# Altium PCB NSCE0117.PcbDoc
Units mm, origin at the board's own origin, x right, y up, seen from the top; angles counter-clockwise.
Board outline 36.5 x 20.1 mm, 2 copper layers (Top Layer, Bottom Layer); 46 components, 30 nets, 110 pads, 14 vias.
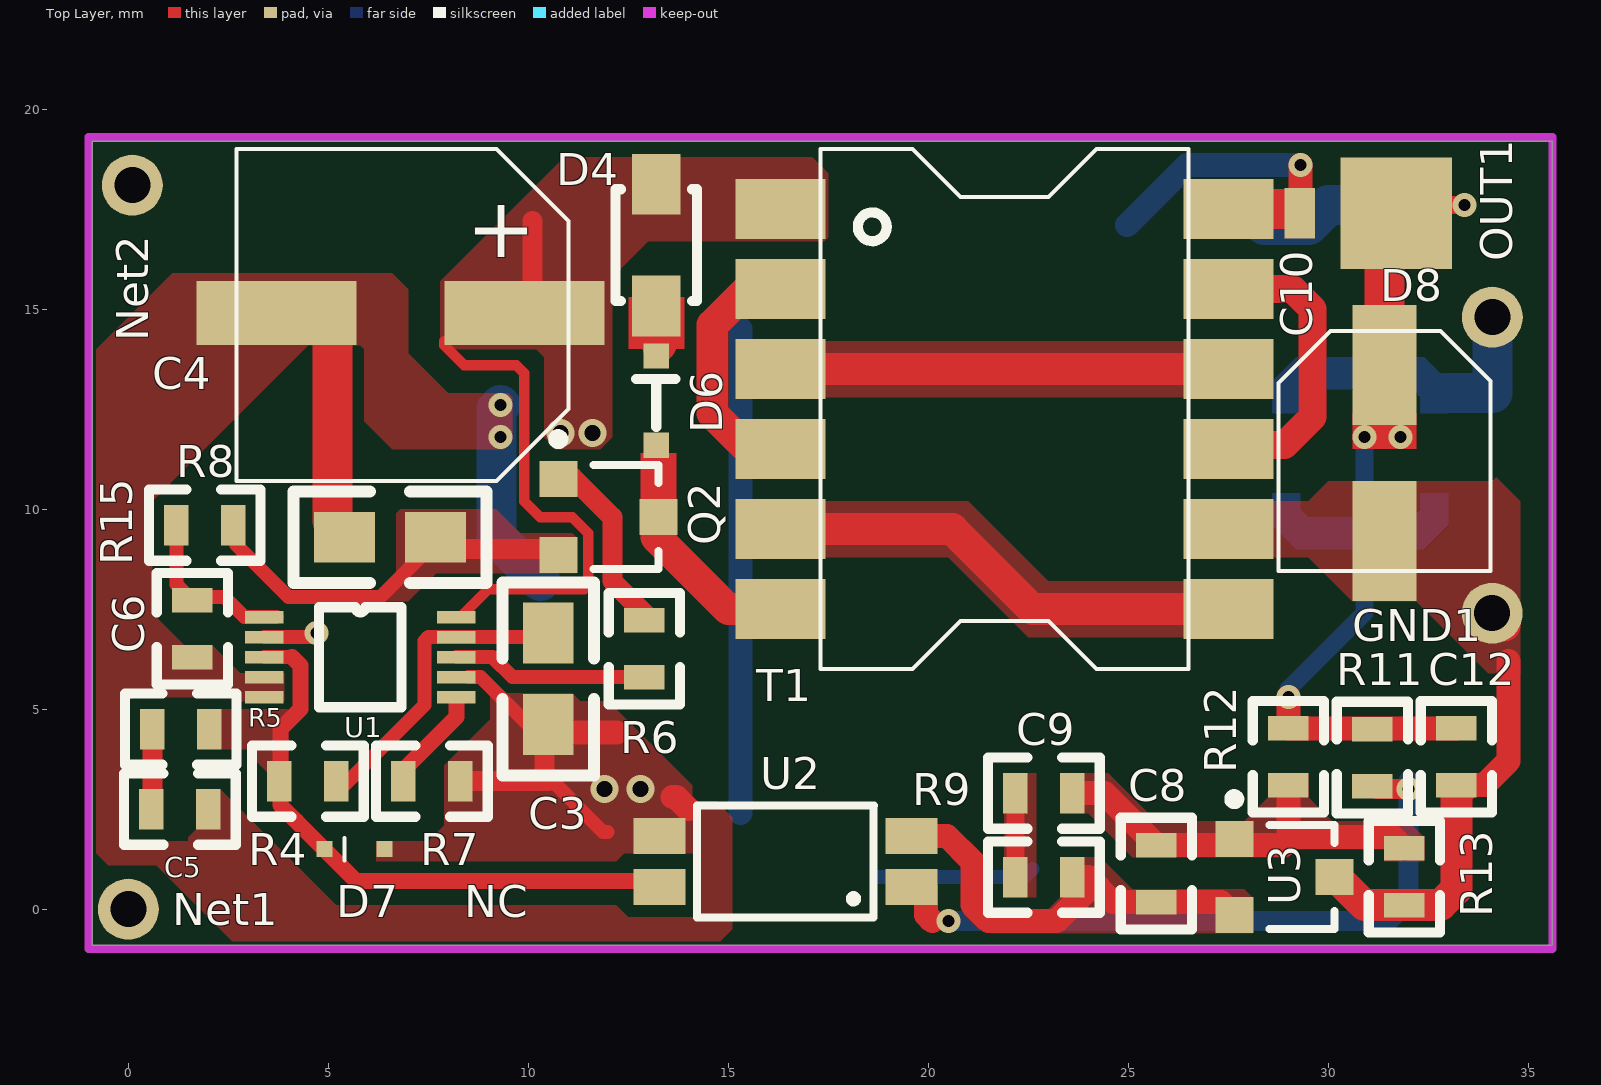
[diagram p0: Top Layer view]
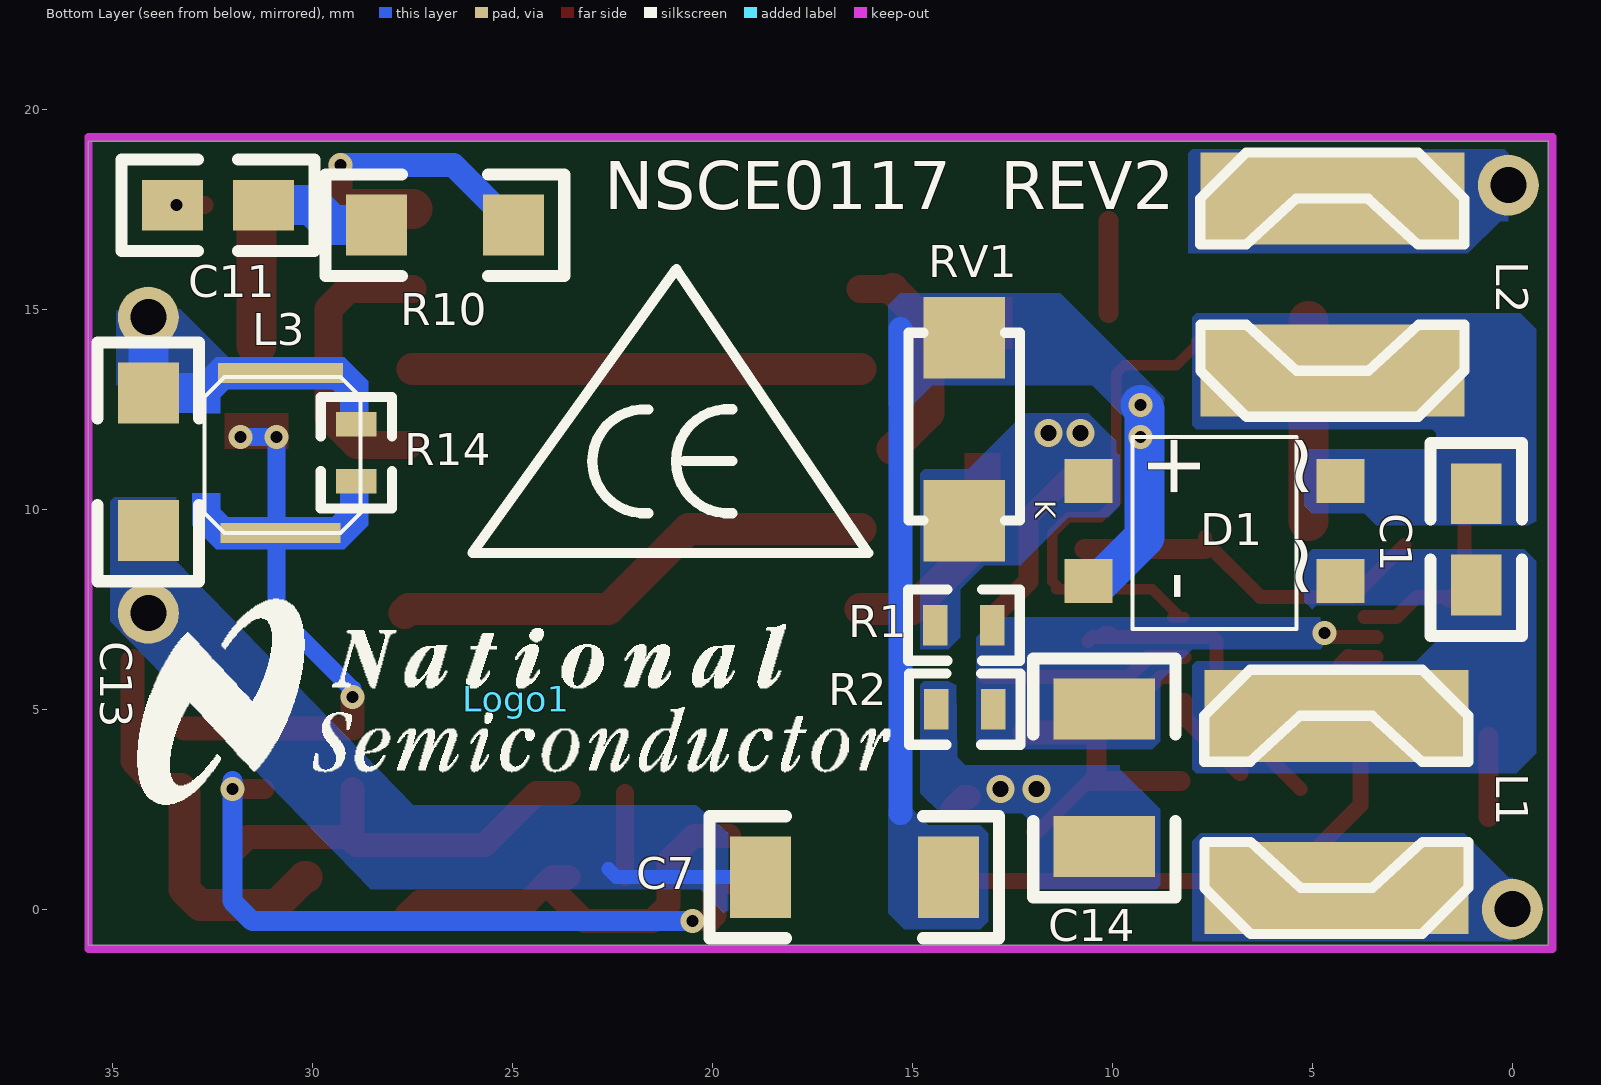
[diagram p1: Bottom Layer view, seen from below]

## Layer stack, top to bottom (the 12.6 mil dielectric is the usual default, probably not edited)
Top Layer: signal copper 0.0356
Dielectric: core 0.32, FR-4, Dk 4.8
Bottom Layer: signal copper 0.0356

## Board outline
-0.9,-0.9 35.6,-0.9 35.6,19.2 -0.9,19.2 -0.9,-0.9

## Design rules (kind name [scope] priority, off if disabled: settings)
AssemblyTestPointUsage [All] p1: valid=2
Clearance [All] p1: gap=0.1
ComponentClearance [All] p1: gap=0.1 collisioncheckmode=3 verticalgap=0.254 showdistances=FALSE
FabricationTestPointUsage TestPointUsage [All] p1: valid=2 allowmultiple=FALSE
FabricationTestpoint Testpoint [All] p1: side=3 testpointundercomponent=TRUE minsize=1.016 maxsize=2.54 preferedsize=1.524 minholesize=0 maxholesize=1.016 preferedholesize=0.813 testpointgrid=0.025 allowsidetop=TRUE allowsidebottom=TRUE usegrid=TRUE gridtolerance=0
MinimumSolderMaskSliver [All] p1: minsoldermaskwidth=0.102
PlaneClearance [All] p1: clearance=0.2
PolygonConnect [All] p1: connectstyle=Direct reliefconductorwidth=0.254 reliefentries=4 polygonreliefangle="90 Angle"
RoutingVias [All] p1: holewidth=0.711 width=1.27 viastyle="Through Hole" minholewidth=0.711 minwidth=1.27 maxholewidth=0.711 maxwidth=1.27
SilkToSilkClearance [All] p1: silktosilkclearance=0.127
SilkscreenOverComponentPads [All] p1: minsilkscreentomaskgap=0.127
SolderMaskExpansion [All] p1: expansion=0.102
Width [All] p1: maxlimit=1.5 minlimit=0.1 preferedwidth=0.254
20 further rules are at their usual default settings.

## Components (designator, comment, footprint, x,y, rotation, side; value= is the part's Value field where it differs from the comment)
C1 "C0805C104K5RACTU" 0805 0.9,8.1 r90 bottom
C3 "C0805C224K3RACTU" 0805 10.5,6.9 r270 top
C4 "EEEFK1H470P" "Panasonic E-Series AluCap" 9.9,14.9 r180 top
C5 "C0603C103K5RACTU" 0603 2,2.5 r180 top
C6 "Not specified" 0603 1.6,6.3 r90 top
C7 "C1808C821KHRAC" 1808 14.1,0.8 r0 bottom
C8 "C0603C101J5GAC" 0603 25.7,1.6 r270 top
C9 "C0603C103K5RACTU" 0603 23.6,2.9 r180 top
C10 "4SVPC150MY" "OS-CON CaseB6 Sanyo" 31.4,13.6 r270 top
C11 "C0805C221J1GAC" 0805 33.5,17.6 r180 bottom
C12 "C0805C104K5RAC" 0603 33.2,3.1 r90 top
C13 "C1206C104K5RAC" 1206 34.1,12.9 r270 bottom
C14 "C1210C226K4PAC" 1210 10.2,5 r270 bottom
D1 "CBRHD-02 LEAD FREE" "Optocoupler CBRHD-xx Central" 4.3,8.2 r90 bottom
D4 "CMHZ4709 LEAD FREE" SOD-123 13.2,16.6 r270 top
D6 "CMDD4448 LEAD FREE" sod-323 13.2,11.6 r90 top (schematic designator D3)
D7 "CMOZ4L7 LEAD FREE" SOD-523 4.9,1.5 r270 top
D8 "SS1P4-M3/84A" DO-220AA 31.7,17.4 r180 top (schematic designator D5)
GND1 "" PCBPin_GoldenNeedle 34.099,7.399 r90 top
L1 "LPS6235-225MLB" Ind_LPS6235 4.4,0.4 r90 bottom
L2 "LPS6235-225MLB" Ind_LPS6235 4.5,17.9 r270 bottom
L3 "LPS4018-xxxMLB" "LPS4018 Coilcraft" 30.8,11.4 r90 bottom
Logo1 "" Logo_Overlay_Medium 24.9,5.25 r180 bottom
Net1 "" PCBPin_GoldenNeedle 0,0 r90 top
Net2 "" PCBPin_GoldenNeedle 0.1,18.1 r90 top
OUT1 "" PCBPin_GoldenNeedle 34.1,14.8 r90 top
Q2 "CPH3427-TL-E" SOT-23 12,9.8 r270 top
R1 "" 0603 13,7.1 r0 bottom
R2 "" 0603 14.4,5 r180 bottom
R4 "" 0603 5.2,3.2 r180 top
R5 "" 0603 0.6,4.5 r0 top
R6 "" 0603 12.9,5.8 r90 top
R7 "" 0603 8.3,3.2 r180 top
R8 "" 0805 5.4,9.3 r0 top
R9 "" 0603 23.6,0.8 r180 top
R10 "" 1206 28.4,17.1 r180 bottom
R11 "" 0603 31.1,4.5 r270 top
R12 "" 0603 29,3.1 r90 top
R13 "" 0603 31.9,0.1 r90 top
R14 "" 0603 28.9,10.7 r90 bottom
R15 "" 0603 1.2,9.6 r0 top
RV1 "SMAJ40CA-E3/61" SMA 13.7,12 r270 bottom
T1 "PCA11/5ER-U07S002" "XFMR-ER11/5 Series Wuerth" 16.3,17.5 r270 top (schematic designator T?)
U1 "LM3481MM/NOPB" MSOP-10 3.4,7.3 r0 top
U2 "TCMT1103" SOP-8 14.5,3.1 r180 top
U3 "LMV431AIMF/NOPB" SOT-23 28.9,0.8 r270 top

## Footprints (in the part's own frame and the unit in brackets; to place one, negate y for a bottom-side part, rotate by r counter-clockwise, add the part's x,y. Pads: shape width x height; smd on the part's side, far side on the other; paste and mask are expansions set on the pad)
0603 [mil]
  rect 24x40 smd: 1(0,0) 2(56,0)
  silkscreen extent -27,-35 83,35
0805 [mil]
  rect 60x50 smd: 1(0,0) 2(90,0)
  silkscreen extent -50,-45 140,45
1206 [mil]
  rect 60x60 smd: 1(0,0) 2(135,0)
  silkscreen extent -50,-50 185,50
1210 [mil]
  rect 60x100 smd: 1(0,0) 2(135,0)
  silkscreen extent -50,-70 185,70
1808 [mil]
  rect 60x80 smd: 1(0,0) 2(185,0)
  silkscreen extent -50,-60 235,60
DO-220AA [mil]
  rect 30x50 smd: 1(95,0)
  rect 110x110 smd: 2(0,0)
Ind_LPS6235 [mm] "Coilcraft LPS6235"
  rect 2.3x6.6 smd: 1(0.127,0) 2(4.427,0)
  silkscreen extent -1.02,-3.3 5.59,3.3
Logo_Overlay_Medium [mm]
  silkscreen extent -9.47,-2.64 9.35,2.51
"LPS4018 Coilcraft" [mm] "LPS4018 Coilcraft"
  rect 0.5x3 smd: 1(-2,0)
  rect 0.5x3.124 smd: 2(2,0)
  Top Layer region: -2.4,1.6 -1.8,2.2 -1,2.2 -1,1.5 -1.4,1.5 -1.6,1.3 -1.6,-1.3 -1.4,-1.5 -1,-1.5 -1,-2.2 -1.8,-2.2 -2.4,-1.6
  Top Layer region: 2.4,-1.6 1.8,-2.2 1,-2.2 1,-1.5 1.4,-1.5 1.6,-1.3 1.6,1.3 1.4,1.5 1,1.5 1,2.2 1.8,2.2 2.4,1.6
  silkscreen extent -2,-2 1.9,1.9
MSOP-10 [mil]
  rect 38x12 smd: 1(0,0) 2(0,-19.7) 3(0,-39.4) 4(0,-59.1) 5(0,-78.8) 6(189,-78.8) 7(189,-59.1) 8(189,-39.4) 9(189,-19.7) 10(189,0)
  silkscreen extent 54,-89 135,10
"Optocoupler CBRHD-xx Central" [mm] "Optocoupler CBRHD-xx Central"
  rect 1.1x1.2 smd: 1(0,0) 2(2.5,0) 3(2.5,6.3) 4(0,6.3)
  silkscreen extent -1.2,1.1 3.6,5.2
"OS-CON CaseB6 Sanyo" [mm] "OS-CON CaseB6 Sanyo"
  rect 3x1.6 smd: 1(0,0) 2(4.4,0)
  silkscreen extent -0.85,-2.65 5.15,2.65
"Panasonic E-Series AluCap" [mm] "Panasonic E-Series AluCap"
  rect 4x1.6 smd: 1(0,0) 2(6.2,0)
  silkscreen extent -1.1,-4.1 7.2,4.2
PCBPin_GoldenNeedle [mil] "PCBPin_GoldenNeedle"
  round 60 hole 35.43: 1(0,0)
SMA [mil]
  rect 80x80 smd: 1(-90,0) 2(90,0)
  silkscreen extent -95,-55 90,55
SOD-123 [mil]
  rect 60x48 smd: 1(-60,0) 2(60,0)
  silkscreen extent -55,-40 55,40
sod-323 [mm]
  rect 0.63x0.63 smd: 1(0,0) 2(2.23,0)
  silkscreen extent 0.46,-0.48 1.65,0.51
SOD-523 [mm]
  rect 0.4x0.4 smd: 1(0,1.5) 2(0,0)
  silkscreen extent -0.28,0.51 0.28,0.51
SOP-8 [mm] "SOP-8 (TCMT1100 Optocoupler)"
  rect 1.3x0.9 smd: 1(-5.08,2.54) 2(-5.08,1.27) 3(1.22,1.27) 4(1.22,2.54)
  silkscreen extent -4.14,0.51 0.28,3.31
SOT-23 [mm] "SOT-23; 3 Leads; Body 3.0 x 2.6 mm, inc. leads (LxW max)"
  rect 0.9x0.95 smd: 1(-0.95,-1.25) 2(0.95,-1.25) 3(0,1.25)
  silkscreen extent -2.07,-1.37 1.3,1.25
"XFMR-ER11/5 Series Wuerth" [mm] "XFMR-ER11/5 Series Wuerth"
  rect 1.5x2.25 smd: 1(0,0) 2(2,0) 3(4,0) 4(6,0) 5(8,0) 6(10,0) 7(10,11.2) 8(8,11.2) 9(6,11.2) 10(4,11.2) 11(2,11.2) 12(0,11.2)
  silkscreen extent -1.5,1 11.5,10.2

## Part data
C1: library part "Cap Semi", "CAP, CERM, 0.1uF, 50V, 10%, X7R, 0805"
C3: library part "Cap Semi", "CAP, CERM, 0.22uF, 25V, 10%, X7R, 0805"
C4: library part T491C, "CAP, AL, 47uF, 50V, +/-20%, 0.68 ohm, SMD"
C5 C9: library part "Cap Semi", "CAP, CERM, 0.01uF, 50V, 10%, X7R, 0603"
C6: library part Cap, "CAP, CERM, 0603"
C7: library part Cap, "CAP, CERM, 820pF, 3000V, 10%, X7R, 1808"
C8: library part "Cap Semi", "CAP, CERM, 100pF, 50V, 5%, C0G/NP0, 0603"
C10: library part T491C, "CAP, Conductive Polymer, 150uF, 4V , 20%, SMD"
C11: library part "Cap Semi", "CAP, CERM, 220pF, 100V, 5%, C0G/NP0, 0805"
C12: library part "Cap Semi", "CAP, CERM, 0.1uF, 50V, 10%, X7R, 0603"
C13: library part "Cap Semi", "CAP, CERM, 0.1uF, 50V, 10%, X7R, 1206"
C14: library part CAP-1210, "CAP, CERM, 22uF, 16V, 10%, X5R, 1210"
D1: library part Bridge1, "Diode, Switching-Bridge, 200V, 0.5A, HD-DIP"
D4: library part "D Zener", "Diode, Zener, 24V, SOD-123"
D6: library part "Diode 1N4001", "Diode, High Speed Switching, 100V, 250mA, SOD-323"
D7: library part "D Zener", "Diode, Zener, 4.7V, SOD-523"
D8: library part DIODE-S-SMA, "Diode, Schottky, 40V, 1A, DO-220AA/SMP"
GND1 Net1 Net2 OUT1: library part PAD70
L1 L2: library part IND-LPS4018, "Inductor, Shielded Drum Core, Ferrite, 2.2mH, 0.11A, 6.4 ohm, SMD"
L3: library part Inductor, "Inductor, Shielded Drum Core, Ferrite, SMD"
Logo1: library part "NSC Logo", "National Semiconductor logo or worldmark"
Q2: library part MOSFET-N, "MOSFET, N-CH, 100V, 1A, SOT-23"
R1: library part Res3, "RES, 100k, 5%, 0603"
R2: library part Res3, "RES, 36k, 5%, 0603"
R4: library part Res3, "RES, 3k3, 5%, 0603"
R5 R15: library part RES1206, "RES, 1k, 5%, 0603"
R6: library part RES1206, "RES, 1R, 5%, 0603"
R7: library part Res3, "RES, 82k, 5%, 0603"
R8: library part Res3, "RES, 1R2, 5%, 0805"
R9: library part Res3, "RES, 1k1, 5%, 0603"
R10: library part RES1206, "RES, 24R, 5%, 1206"
R11: library part RES1206, "RES, 110R, 5%, 0603"
R12: library part RES1206, "RES, 5.62k, 1%, 0603"
R13: library part RES1206, "RES, 3.32k, 1%, 0603"
R14: library part RES0603, "RES, 0R, 5%, 0603"
RV1: library part "Res Varistor", "Transient Suppressor, 71.4V, SMA"
T1: library part XFMR-NSCE0117, "Transformer"
U1: library part LM3481, "High Efficiency Low-Side N-Channel Controller for Switching Regulators"
U2: library part OPTO-NEC-PS2501, "Optocoupler, CTR 100% to 200%"
U3: library part LM431, "1.24V Shunt Regulator, 1%, SOT-23"

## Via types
v1: diameter 0.6, hole 0.3, Top Layer to Bottom Layer, 10 vias
v2: diameter 0.7, hole 0.4, Top Layer to Bottom Layer, 4 vias

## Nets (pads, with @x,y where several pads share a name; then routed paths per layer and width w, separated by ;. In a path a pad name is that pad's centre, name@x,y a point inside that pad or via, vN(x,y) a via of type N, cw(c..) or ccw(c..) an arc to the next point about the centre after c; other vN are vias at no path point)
GND: C3.2 C4.2 C5.1 C6.1 C7.1 C14.2 D1.4 D7.1 R2.1 R7.1 R8.1 RV1.1 U1.4 U1.5 U1.7 U2.3 | length 32.4
  Top Layer w0.35: U1.7@8.5,5.8 8.8,5.8 C3.2@10.4,4.2 ; 10.4,3.4 11.87,1.93 11.98,1.93
  Top Layer w0.5: R7.1 10.5,3.2 10.4,3.3 C3.2@10.4,4.414
  Top Layer w0.6: C3.2@10.5,4.414 12.2,4.414 ; 13.6,2.8 13.7,2.8 14,2.5
  Top Layer w1: R8.1@5.1,9.7 C4.2@5.1,14.7
  Bottom Layer w0.6: 15.3,2.4 15.3,14.5
  Bottom Layer w1: v1(9.3,12.6) 9.2,12.5 9.2,9.3 D1.4@10.3,8.2
  other v1: 9.3,11.8
  other v2: 11.9,3 12.8,3
GND1: C7.2 C10.2 C12.1 C13.2 GND1.1 R13.1 T1.8 U3.3 | length 14.2
  Top Layer w0.6: C12.1@33.4,3.1 33.9,3.1 34.5,3.7 34.5,6.2
  Top Layer w0.8: U3.3 30.2,0.8 30.9,0.1 32.8,0.1 33.2,0.5 33.2,2.9 C12.1@33.3,3 ; GND1.1 GND1.1@34.4,7.098
  Bottom Layer w0.35: C7.2 22.4,0.8 22.6,1
NetC1_1: C1.1 D1.1 L1.2
NetC1_2: C1.2 D1.2 L2.2
NetC3_1: C3.1 R4.1 U1.9 | length 8
  Top Layer w0.35: R4.1@5.3,3 6.2,3.9 7.4,5.1 7.4,6.7 7.5,6.8 U1.9 ; U1.9 10.5,6.8 C3.1@10.6,6.7 ; C3.1@10.05,6.9 C3.1@10.2,6.9
NetC4_1: C4.1 D1.3 D4.1 R1.2 RV1.2 T1.1 U1.10 | length 15
  Top Layer w0.254: C4.1@7.9,14.2 7.9,14.1 8.4,13.6 9.7,13.6 9.9,13.4 9.9,10.2 10.3,9.8 11.1,9.8 11.5,9.4 11.5,8.2 11.4,8.1 11.4,8 9,8 U1.10@8.3,7.3 ; U1.10 U1.10@8.5,7.3
  Top Layer w0.5: C4.1@10.1,14.9 10.1,17.2
  other v2: 10.8,11.9 11.6,11.9
NetC5_2: C5.2 R5.1 | length 2
  Top Layer w0.5: C5.2@0.6,2.3 R5.1@0.6,4.3
NetC6_2: C6.2 R15.1 U1.1 | length 4.3
  Top Layer w0.35: R15.1 1.2,8.122 C6.2@1.522,7.8 ; C6.2@1.5,7.8 C6.2@1.522,7.8 ; C6.2 C6.2@1.522,7.8 ; 2.3,7.8 C6.2@1.522,7.8 ; 2.4,7.8 2.9,7.3 U1.1 ; U1.1@3.5,7.3 U1.1@3.7,7.3
NetC8_1: C8.1 C9.1 R12.1 R13.2 U3.1 | length 10.3
  Top Layer w0.6: C9.1 24.4,2.9 C8.1 28.9,1.6 29.1,1.8 31.622,1.8 R13.2 ; 29,1.7 R12.1@29,3
NetC8_2: C8.2 R9.1 U2.2 U3.2 | length 11.3
  Top Layer w0.35: U2.2@19.6,1.7 U2.2@20.2,1.7
  Top Layer w0.6: U2.2 20.47,1.83 21.1,1.2 21.1,0.1 21.5,-0.3 23.2,-0.3 24,0.5 ; R9.1 24,0.8 24.622,0.178 27.322,0.178 U3.2
NetC9_2: C9.2 R9.2 | length 2.1
  Top Layer w0.45: R9.2 C9.2
NetC10_1: C10.1 C11.1 C12.2 D8.2 L3.1 R11.1 R12.2 R14.1 | length 16.8
  Top Layer w0.45: D8.2@32.7,17.6 v1(33.4,17.6)
  Top Layer w0.6: v1(29,5.3) R12.2 C12.2
  Top Layer w1: C10.1@31.4,14.1 D8.2@31.4,17.2
  Bottom Layer w0.45: v1(29,5.3) 29,5.5 30.9,7.4 L3.1@30.9,9.4 ; L3.1@30.9,9.6 30.9,11.7 v1(30.9,11.8) v1(31.8,11.8)
NetC11_2: C11.2 R10.1 | length 3
  Bottom Layer w1: R10.1 29.5,17.1 30,17.6 C11.2
NetC13_1: C13.1 L3.2 OUT1.1 R14.2 | length 3.1
  Bottom Layer w1: 32.9,12.9 C13.1 OUT1.1
NetC14_1: C14.1 R1.1 R2.2 U1.2 | length 1.3
  Top Layer w0.35: U1.2 4.6,6.8 v1(4.7,6.9)
NetD4_2: D4.2 D6.2 | length 0.1
  Top Layer w0.8: D6.2@13.25,14.05 D6.2@13.3,14.1
NetD6_1: D6.1 Q2.3 T1.6 | length 3.8
  Top Layer w0.8: 13.2,9.3 15,7.5 T1.6
NetD7_2: D7.2 R4.2 R5.2 U1.3 U2.4 | length 15.1
  Top Layer w0.35: U1.3 4.099,6.299
  Top Layer w0.4: 4.099,6.299 4.3,6.098 4.3,5 3.8,4.5 3.8,2.6 4.2,2.2 D7.2 5.7,0.7 U2.4@13.4,0.7
NetD8_1: D8.1 R10.2 T1.12 | length 7.7
  Top Layer w0.6: D8.1@29.3,17.413 v1(29.3,18.6)
  Top Layer w1: T1.12 D8.1@29.1,17.5
  Bottom Layer w0.6: R10.2 26.471,18.6 v1(29.3,18.6)
NetL1_1: L1.1 Net1.1
NetL2_1: L2.1 Net2.1 | length 0.4
  Bottom Layer w0.254: Net2.1@0.1,17.8 Net2.1@0.1,18.2
NetQ2_2: Q2.1 R6.2 | length 4.6
  Top Layer w0.35: R6.2@12.978,7.322 R6.2@13.1,7.322
  Top Layer w0.5: Q2.1@10.9,10.8 11.1,10.8 12.1,9.8 12.1,8.2 R6.2@12.978,7.322
NetQ2_3: Q2.2 R8.2 R15.2 | length 9.2
  Top Layer w0.35: R15.2@2.7,9.1 4,7.8 6.3,7.8 7.686,9.186 R8.2
  Top Layer w0.5: R8.2@7.7,9 Q2.2@10.7,9
NetR6_1: R6.1 U1.8 | length 5.2
  Top Layer w0.35: U1.8 9.101,6.299 9.6,5.8 R6.1@13.2,5.8
NetR7_2: R7.2 U1.6 | length 2.4
  Top Layer w0.4: R7.2@6.8,3.4 8.201,4.801 U1.6@8.201,5.199
NetR11_2: R11.2 U2.1 | length 16.8
  Top Layer w0.35: U2.1 U2.1@19.94,0.56
  Top Layer w0.5: R11.2@31.2,3 v1(32,3)
  Top Layer w0.6: U2.1@19.94,0.56 19.94,-0.14 20.1,-0.3
  Bottom Layer w0.5: v1(20.5,-0.3) 31.5,-0.3 32,0.2 v1@32,3.2
NetT1_2: T1.2 T1.4 | length 5.5
  Top Layer w0.7: T1.2@15.5,15.5 T1.2
  Top Layer w0.8: T1.4@15.5,11.5 14.6,12.4 14.6,14.6 T1.2@15.5,15.5
NetT1_3: T1.3 T1.10 | length 11.2
  Top Layer w0.8: T1.3 T1.10
NetT1_5: T1.5 T1.7 | length 12.3
  Top Layer w0.8: T1.5 20.6,9.5 22.6,7.5 27.6,7.5 T1.7@27.7,7.4
NetT1_9: T1.9 T1.11 | length 7.3
  Top Layer w0.7: T1.11 29.1,15.5 29.6,15 29.6,12.3 28.9,11.6 T1.9@27.6,11.6

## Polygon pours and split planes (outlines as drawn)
GND on Top Layer "Top Layer-No Net 1" (solid, pour order 1000): 6.8,15.7 6.6,15.9 6.5,15.9 1.1,15.9 -0.796,14.004 -0.796,6.504 1.496,6.504 1.5,6.5 0.6,7.4 0.6,10.2 4.5,14.1 5.7,14.1
NetC8_1 on Top Layer "Top Layer-No Net 11" (solid, pour order 1006): 29.5,2.8 30.7,1.6 25.3,1.6 25.3,2.1 28.2,2.1 28.7,2.6 28.7,2.8 29.5,2.8
NetC8_1 on Top Layer "Top Layer-No Net 10" (solid, pour order 1005): 23.3,3.4 24.5,3.4 25.7,2.2 27.9,2.2 28.5,2.8 28.5,3.4 29.5,3.4 29.5,2.9 29.5,2.6 29.9,2.2 31.8,2.2 32,2.2 32.4,1.8 32.4,1.2 31.4,1.2 31.4,1.5 29.2,1.5 29,1.3 25.1,1.3 24,2.4 23.3,2.4 23.3,3.4
NetC8_2 on Top Layer "Top Layer-No Net 9" (solid, pour order 1004): 23.3,1.3 23.9,1.3 24.3,1.3 25.1,0.5 27.8,0.5 27.9,0.5 28.1,0.3 28.1,-0.6 21.4,-0.6 21.6,-0.4 21.6,0 23,0 23.3,0.3 23.3,1.3
NetC9_2 on Top Layer "Top Layer-No Net 8" (solid, pour order 1003): 21.9,3.4 22.7,3.4 22.7,0.3 21.9,0.3 21.9,3.4
NetT1_5 on Top Layer "Top Layer-No Net 7" (solid, pour order 1002): 15.2,10.2 20.6,10.2 21,10.2 23,8.2 28.6,8.2 28.6,6.8 22.6,6.8 22.5,6.8 20.5,8.8 15.2,8.8 15.2,10.2
NetT1_3 on Top Layer "Top Layer-No Net 3" (solid, pour order 1001): 15.2,14.2 28.6,14.2 28.6,12.8 15.2,12.8 15.2,14.2
GND1 on Top Layer "Top Layer-No Net 6" (solid, pour order 1002): 26.4,8.8 28.6,8.8 29.1,8.8 29.5,8.8 30.6,7.7 32.2,7.7 34,5.9 34.8,5.9 34.8,10.2 34.2,10.8 34.1,10.7 30,10.7 29.5,10.2 26.4,10.2 26.4,8.8
GND on Top Layer "Top Layer-No Net 5" (solid, pour order 1001): 6.2,1.7 8,1.7 8,3 8,2.9 9.7,1.2 6.2,1.2 6.2,1.7
NetD7_2 on Top Layer "Top Layer-No Net 4" (solid, pour order 1004): 2.1,5 4,5 4,2.9 4.1,2.8 3,3.9 3,4 2.1,4 2.1,5
NetC4_1 on Top Layer "Top Layer-No Net 1" (solid, pour order 1000): 10.4,11.9 10.4,11.8 10.7,11.5 11.7,11.5 11.8,11.5 12,11.7 12.1,11.8 12.1,15.8 10.2,15.8 10.1,15.9 10.2,15.8 10.2,14.1 10.2,14 10.4,13.8 10.4,11.9
GND on Top Layer "Top Layer-No Net 1" (solid, pour order 1001): 9.3,12.9 9.5,12.9 9.6,12.8 9.6,11.7 9.4,11.5 6.8,11.5 6.6,11.5 6.2,11.9 5.9,12.2 5.9,14 5.8,14.1 5.7,14.1 5.7,15.7 6.7,15.7 6.8,15.7 7,15.5 7,14 7,13.9 8,12.9 9.3,12.9
NetQ2_3 on Top Layer "Top Layer-No Net 1" (solid, pour order 1002): 6.8,10 9.2,10 9.5,9.7 9.8,9.4 10.5,9.4 11.1,9.4 11.2,9.3 11.2,8.4 7.7,8.4 7,7.7 6.4,7.7 6.4,7.9 6.3,8 6.7,8.4 6.7,8.7 6.7,9.9 6.8,10
NetC4_1 on Top Layer "Top Layer-No Net 1" (solid, pour order 1003): 7.8,15.7 10.9,18.8 11.2,18.8 17.1,18.8 17.5,18.4 17.5,16.8 17.4,16.7 13,16.7 12.1,15.8 12,15.7 12,14.6 12,14.2 11.8,14 7.9,14 7.8,14.1 7.8,15.7
GND on Top Layer "Top Layer-No Net 2" (solid, pour order 1000): 3.9,5.9 2.8,5.9 2.1,6.6 -0.7,6.6 -0.9,6.4 -0.9,1.5 -0.5,1.1 0.7,1.1 2.7,-0.9 14.7,-0.9 15.1,-0.5 15.1,2.3 14.7,2.7 14.1,2.7 14.1,3.1 12,5.2 11.3,5.2 11.1,5.4 9.4,5.4 9.252,5.548 9.052,5.548 9.052,4.752 7.9,3.6 7.9,2.1 7.4,1.6 7.4,1.2 12.2,1.2 12.4,1.4 14.1,1.4 14.3,1.2 14.3,-0.1 14.2,-0.2 12.5,-0.2 12.2,0.1 5.2,0.1 5.1,0.2 2.3,3 1.7,3 1.7,2 1.5,1.8 1.5,1.7 0.1,1.7 -0.1,1.9 0,2 0,5.2 0.1,5.3 2.7,5.3 2.8,5.2 3.9,5.2
GND1 on Bottom Layer "Bottom Layer-No Net 8" (solid, pour order 1007): 28.543,0.5 34.566,6.7 35.051,7.2 35.051,10.2 34.954,10.3 33.4,10.3 33.4,8.7 27.474,2.6 20.4,2.6 19.6,1.9 19.6,-0.2 20.3,0.5
NetC13_1 on Bottom Layer "Bottom Layer-No Net 12" (solid, pour order 1001): 33.3,15 32.1,13.8 32,13.8 32,13.2 32.1,13.1 34.9,13.1 34.9,15.1 34.8,15 33.3,15
NetL1_1 on Bottom Layer "Top Layer-No Net 1" (solid, pour order 1005): -0.6,0.7 0,0.7 1.2,1.9 7.6,1.9 7.8,1.9 8,1.7 8,-0.6 8,-0.8 7.9,-0.9 0,-0.9 0,0.7 0.1,0.8
NetL2_1 on Bottom Layer "Top Layer-No Net 1" (solid, pour order 1006): 8.1,19.1 8.1,19 8.1,16.5 8.1,16.4 1.113,16.4 0.303,17.2 0.1,17.2 0.1,19.1 0.201,19 7.999,19
NetC14_1 on Bottom Layer "Top Layer-No Net 1" (solid, pour order 1007): 4.7,6.5 8,6.5 8.8,5.7 8.8,4.2 9,4 11.4,4 12.3,4 13.1,4 13.4,4.1 13.4,6.8 12.9,7.3 4.8,7.3
GND on Bottom Layer "Top Layer-No Net 1" (solid, pour order 1008): 14.1,5.7 14.8,5.7 14.797,5.4 14.797,2.9 14.289,2.4 12.256,2.4 12.052,2.2 12.052,0.7 11.849,0.5 8.902,0.5 8.8,0.6 8.8,2.5 9.816,3.5 9.816,3.6 13.679,3.6 13.882,3.8 13.9,5.6
GND on Bottom Layer "Top Layer-No Net 1" (solid, pour order 1009): 13.1,1.9 13.3,2.1 14.6,2.1 15,2.5 15.6,2.5 15.6,-0.1 15.2,-0.5 13.3,-0.5 13.1,-0.3 13.1,1.9
GND on Bottom Layer "Top Layer-No Net 1" (solid, pour order 1010): 8.7,12.7 8.7,12.8 11.3,15.4 15.1,15.4 15.3,15.4 15.6,15.1 15.6,12.6 15,12.6 14.5,13.1 14.2,13.1 10.5,13.1 9.7,12.3
NetC4_1 on Bottom Layer "Top Layer-No Net 1" (solid, pour order 1011): 9.9,11.4 9.9,11.7 10.6,12.4 12.2,12.4 13.6,11 14.7,11 14.8,10.9 14.8,6.5 14.1,6.5 13.8,6.8 13.8,8 13.2,8.6 12.3,8.6 11.1,9.8 10.1,9.8 9.8,10.1 9.8,11.5
NetC1_1 on Bottom Layer "Top Layer-No Net 1" (solid, pour order 1012): 8,3.7 8,3.5 7.9,3.4 1.1,3.4 -0.1,3.4 -0.6,3.9 -0.6,8.7 -0.3,9 4.9,9 5,9 5.2,8.8 5.2,7.8 5.2,7.7 5,7.5 4.9,7.6 2.2,7.6 2.1,7.6 1.9,7.4 1.9,6.8 1.9,6.7 2.4,6.2 7.9,6.2 8,6.1 8,3.7
NetC1_2 on Bottom Layer "Top Layer-No Net 1" (solid, pour order 1013): 8,12.1 8,14.8 7.9,14.9 -0.2,14.9 -0.6,14.5 -0.6,9.7 -0.4,9.6 3.4,9.6 3.7,9.9 5,9.9 5.2,10.1 5.2,11.4 5.1,11.5 2.1,11.5 1.9,11.7 1.9,11.9 2,12 7.9,12

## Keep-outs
Keep-Out Layer:
  lines w0.2: -1,-1 -1,19.3 35.6,19.3 35.6,-1 -1,-1
  text ".Layer_Name" at 13.733,-28.142 h1.52
  text "880" at 78.261,-28.142 h1.52

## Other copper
Top Layer:
  rectangle net NetD4_2: 12.5,14 13.9,15.3
  rectangle net NetD6_1: 12.8,9.4 13.7,11.4
  rectangle net NetC10_1: 30.6,11.5 32.2,12.4
  text ".Layer_Name" at 13.733,-28.142 h1.52
  text "880" at 78.261,-28.142 h1.52
Bottom Layer:
  text ".Layer_Name" at 13.733,-28.142 h1.52
  text "880" at 78.261,-28.142 h1.52

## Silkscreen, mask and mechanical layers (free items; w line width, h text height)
Top Overlay:
  text "NC" at 8.4,-0.2 h0.8
  text ".Layer_Name" at 13.733,-28.142 h1.52
  text "880" at 78.261,-28.142 h1.52
Bottom Overlay:
  lines w0.25: 19.5,11.2 20.7,11.2 ; 16.1,8.9 26,8.9 20.9,16 16.1,8.9
  lines w0.254: 19.5,9.9 ccw(c19.6,11.2) 19.501,12.5 ; 21.6,9.9 ccw(c21.7,11.196) 21.6,12.492
  text "REV2" at 12.8,17.5 h1.2
  text "NSCE0117" at 22.7,17.5 h1.2
  text ".Layer_Name" at 13.733,-28.142 h1.52
  text "880" at 78.261,-28.142 h1.52
Top Paste:
  text ".Layer_Name" at 13.733,-28.142 h1.52
  text "881" at 78.261,-28.142 h1.52
Bottom Paste:
  text ".Layer_Name" at 13.733,-28.142 h1.52
  text "881" at 78.261,-28.142 h1.52
Top Solder:
  text ".Layer_Name" at 13.733,-28.142 h1.52
  text ".Layer_Name" at 13.733,-28.142 h1.52
  text "880" at 78.261,-28.142 h1.52
Bottom Solder:
  text ".Layer_Name" at 13.733,-28.142 h1.52
  text "880" at 78.261,-28.142 h1.52
Drill Guide:
  text ".Layer_Name" at 13.733,-28.142 h1.52
  text "880" at 78.261,-28.142 h1.52
M1 Board Outline:
  lines w0.2: -1,-1 35.6,-1 35.6,19.3 -1,19.3 -1,-1
  text ".Layer_Name" at 13.733,-28.142 h1.52
  text "880" at 78.261,-28.142 h1.52
M2 Dimensions:
  rectangle: -0.936,-13.588 2.239,-10.413
  rectangle: 2.239,-16.763 11.764,-13.588
  lines w0.178: -0.936,-13.588 24.464,-13.588 ; 2.239,-16.763 2.239,-10.413 ; 5.414,-16.763 5.414,-10.413 ; 11.764,-16.763 11.764,-10.413 ; 18.114,-16.763 18.114,-10.413 ; -0.936,-16.763 24.464,-16.763 24.464,-10.413 -0.936,-10.413 -0.936,-16.763
  lines w0.254: -0.936,-18.414 -0.936,-17.906 ; 0.588,-18.668 -0.936,-18.16 ; 0.588,-17.652 -0.936,-18.16 ; 5.264,-18.16 -0.936,-18.16 ; 18.265,-18.16 24.464,-18.16 ; 22.94,-18.668 24.464,-18.16 ; 22.94,-17.652 24.464,-18.16 ; 24.464,-18.414 24.464,-17.906
  text "25.4 (mm)" at 5.518,-19.074 h1.52
  text ".Layer_Name" at 13.733,-28.142 h1.52
  text "880" at 78.261,-28.142 h1.52
M9 Title Sheet:
  drawing of 63 lines, arcs and shapes, not listed
  text "1" at 17.869,197.791 h1.78
  text "2" at 81.258,197.791 h1.78
  text "3" at 144.488,197.791 h1.78
  text "4" at 208.157,197.791 h1.78
  text "5" at 271.631,197.791 h1.78
  text "6" at 335.258,197.791 h1.78
  text "A" at -11.502,168.758 h1.78
  text "B" at -11.502,108.306 h1.78
  text "B" at 364.418,108.306 h1.78
  text "C" at -11.502,47.981 h1.78
  text "C" at 364.418,47.981 h1.78
  text "A" at 365.688,22.277 h1.78
  text "PROJECT TITLE:" at 287.202,0.712 h1.14
  text ".PRJ_Title" at 288.472,-2.674 h1.78
  text "FILE NAME:" at 287.202,-6.933 h1.14
  text ".PCB_File_Name_No_Path" at 288.472,-9.981 h1.78
  text "D" at -11.502,-12.217 h1.78
  text "D" at 364.418,-12.217 h1.78
  text "FAB DRAWING NUMBER:" at 287.202,-14.299 h1.14
  text "551" at 288.472,-18.236 h1.78
  text ".PRJ_BasePN" at 293.425,-18.236 h1.78
  text ".PCB_MinorRev" at 303.839,-18.236 h1.78
  text "National Semiconductor and/or its licensors do not warrant the accuracy or completeness of this specification" at 160.976,-21.712 h1.14
  text "DESIGNED FOR:" at 287.202,-22.173 h1.14
  text "or any information contained therein. National and/or its licensors do not warrant that this design will meet" at 159.834,-24.574 h1.14
  text ".PRJ_Customer" at 288.472,-25.729 h1.78
  text "the specifications, will be suitable for your application or fit for any particular purpose, or will operate in" at 159.834,-27.435 h1.14
  text ".Layer_Name" at 13.733,-28.142 h1.52
  text "880" at 78.261,-28.142 h1.52
  text "ALTIUM DESIGNER VERSION:" at 326.445,-29.793 h1.14
  text "an implementation. National and/or its licensors do not warrant that the design is production worthy. You should" at 159.834,-30.297 h1.14
  text ".print_Scale" at 288.472,-32.384 h1.78
  text "completely validate and test your design implementation to confirm the system functionality for your application." at 160.976,-33.159 h1.14
  text ".Application_BuildNumber" at 327.715,-33.18 h1.78
  text "1" at 17.869,-38.429 h1.78
  text "2" at 81.258,-38.429 h1.78
  text "3" at 144.488,-38.429 h1.78
  text "4" at 208.157,-38.429 h1.78
  text "5" at 271.631,-38.429 h1.78
  text "6" at 335.258,-38.429 h1.78
M11 Gerber Information:
  lines w0.178: -8.34,-29.963 159.3,-29.963 ; -8.34,-24.798 159.351,-24.798 ; -8.34,-19.633 -8.34,-35.127 93.387,-35.127 159.351,-35.127 159.351,-19.633 -8.327,-19.633 -8.327,-35.127 31.69,-35.127 ; 54.271,-35.127 54.271,-19.633 ; 123.588,-35.127 123.588,-29.963
  text "ALL ARTWORK VIEWED FROM TOP SIDE" at -6.727,-22.99 h1.52
  text "PROJECT NAME =" at 56.176,-22.99 h1.52
  text ".PRJ_Title" at 78.261,-22.99 h1.52
  text "LAYER NAME =" at -6.727,-28.142 h1.52
  text "ARTWORK #    =" at 56.176,-28.142 h1.52
  text ".prj_BasePN" at 82.732,-28.142 h1.52
  text ".pcb_minorRev" at 91.952,-28.142 h1.52
  text "NATIONAL SEMICONDUCTOR" at 125.391,-33.066 h1.52
  text "PLOT NAME =" at -6.727,-33.371 h1.52
  text ".plot_File_Name" at 13.733,-33.371 h1.52
  text "GENERATED    :" at 56.176,-33.371 h1.52
  text ".Print_Date" at 78.261,-33.371 h1.52
  text ".Print_Time" at 96.778,-33.371 h1.52
Drill Drawing:
  text ".Legend" at 41,-0.4 h1.52
  text ".Layer_Name" at 13.733,-28.142 h1.52
  text "880" at 78.261,-28.142 h1.52

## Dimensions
-1,-1 to -1,19.3 on M2 Dimensions
-1,-1 to 35.6,-1 on M2 Dimensions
